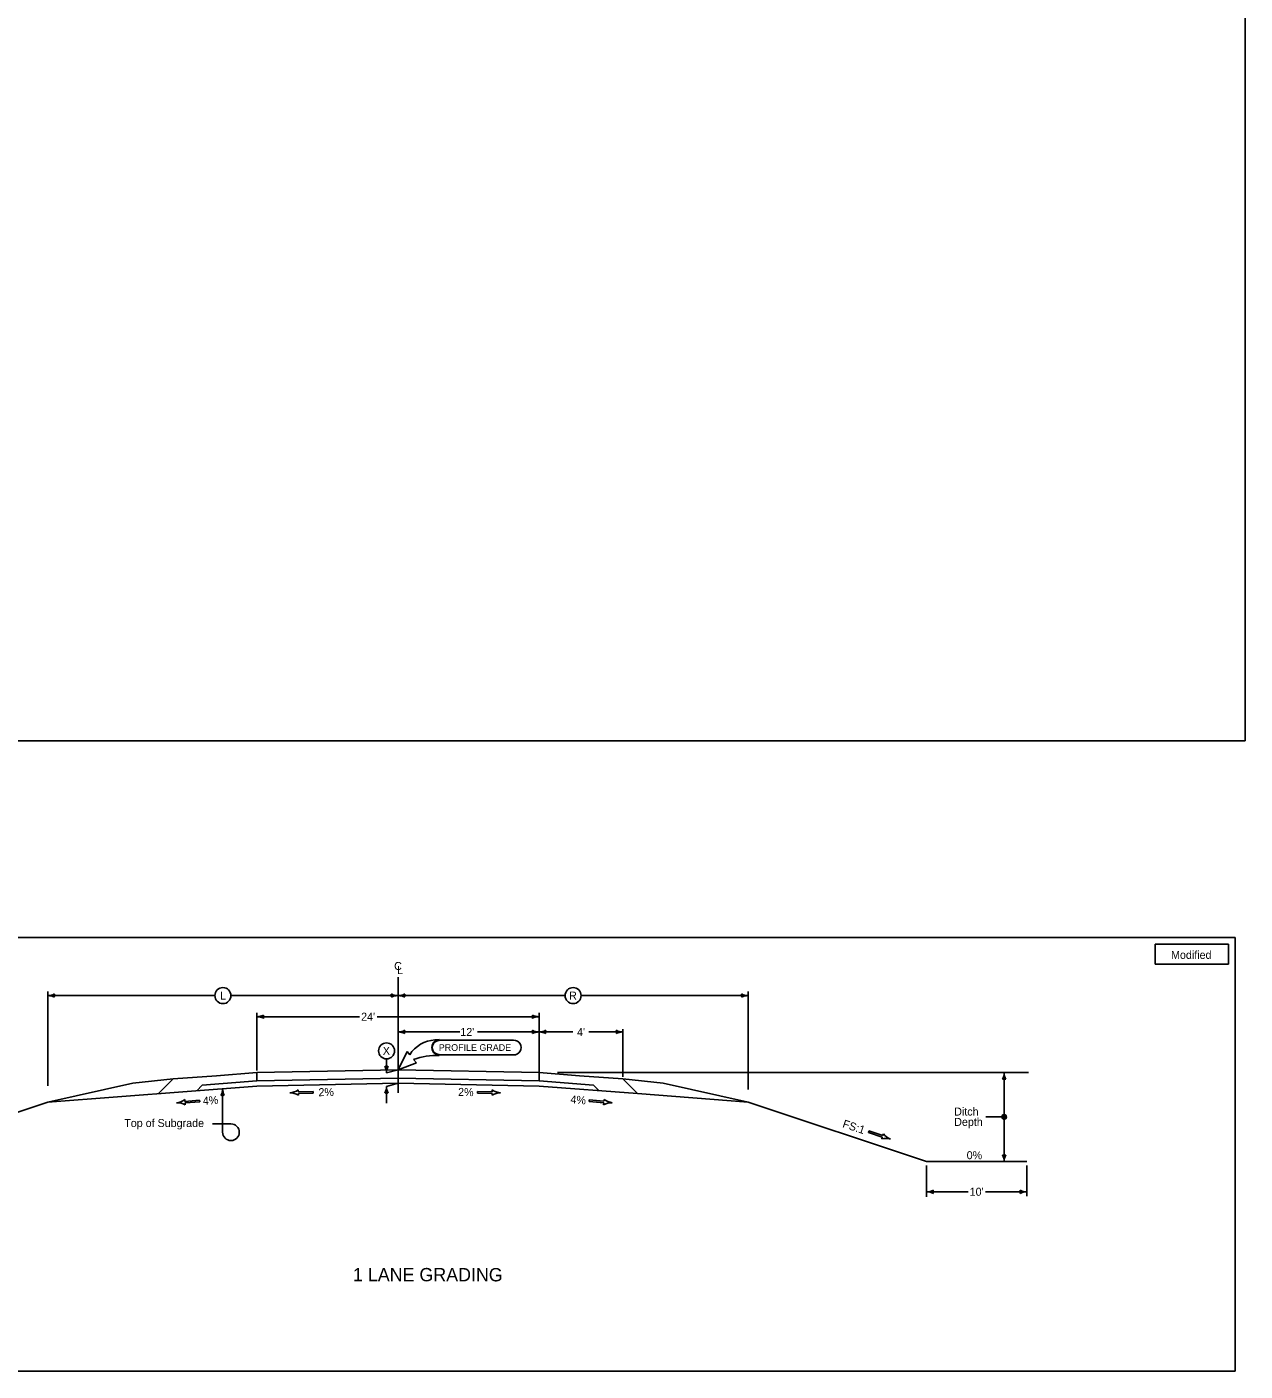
# Model space of a CAD drawing. Extents: x 10133 to 81668, y 6979 to 11018.
# Drawn here: x 11441 to 13268, y 6979 to 8994 of the extents above; entities that cross this region are included whole.
import ezdxf

# ---------------------------------------------------------------- set-up
doc = ezdxf.new("R2010")
doc.units = 0
for name, color, linetype in [('brgPreRevetmentShaded', 7, 'Continuous'), ('brgPreStructureAlternateA', 7, 'Continuous'), ('brgPreStructureNew', 7, 'Continuous'), ('DisFieldPointElev', 7, 'Continuous'), ('dsnCellElements', 7, 'Continuous'), ('dsnShtPlotShapeBatchPrint', 7, 'Continuous'), ('dsnStdShading', 7, 'Continuous'), ('Level 11', 7, 'Continuous')]:
    doc.layers.add(name, color=color, linetype=linetype)

msp = doc.modelspace()

# ---------------------------------------------------------------- linework, layer by layer
at = {"layer": 'brgPreRevetmentShaded'}
for p, q in [((11660.4, 7417), (11599.9, 7410.9)), ((11660.4, 7417), (11638.5, 7395)), ((11725.6, 7421.9), (11660.4, 7417)), ((11725.6, 7421.9), (11786, 7426.5)), ((11786, 7426.5), (11997.6, 7430.8)), ((11786, 7426.5), (11786, 7414)), ((11786, 7414), (11997.6, 7418.2)), ((11997.6, 7430.8), (12209.1, 7426.5)), ((11997.6, 7418.2), (12209.1, 7414)), ((12269.5, 7421.9), (12209.1, 7426.5)), ((12269.5, 7421.9), (12334.7, 7417)), ((12334.7, 7417), (12356.6, 7395)), ((11599.9, 7410.9), (11472.6, 7382.4)), ((11472.6, 7382.4), (11786, 7406.3)), ((11704.2, 7407.8), (11695.9, 7399.4)), ((11704.2, 7407.8), (11786, 7414)), ((11786, 7406.3), (11997.6, 7410.5)), ((12209.1, 7406.3), (11997.6, 7410.5)), ((12290.9, 7407.8), (12209.1, 7414)), ((12356.6, 7395), (12209.1, 7406.3)), ((12290.9, 7407.8), (12299.3, 7399.4))]:
    msp.add_line(p, q, dxfattribs=at)
at = {"layer": 'brgPreStructureAlternateA'}
msp.add_line((11472.6, 7382.4), (11205, 7293.2), dxfattribs=at)
at = {"layer": 'brgPreStructureNew'}
for p, q in [((11997.6, 7396.4), (11997.6, 7569.8)), ((11472.6, 7406.9), (11472.6, 7547.9)), ((11472.6, 7541.9), (11723.1, 7541.9)), ((11747.1, 7541.9), (11997.6, 7541.9)), ((12248.1, 7541.9), (11997.6, 7541.9)), ((12522.6, 7541.9), (12272.1, 7541.9)), ((12522.6, 7401), (12522.6, 7547.9)), ((11786, 7516.3), (11786, 7429.9)), ((12209.1, 7516.3), (12209.1, 7414)), ((11786, 7510.3), (11940, 7510.3)), ((11966.4, 7510.3), (12209.1, 7510.3)), ((12090.4, 7487.4), (11997.6, 7487.4)), ((12209.1, 7487.4), (12116.9, 7487.4)), ((12209.1, 7487.4), (12259.9, 7487.4)), ((12283.9, 7487.4), (12334.7, 7487.4)), ((12334.7, 7491.4), (12334.7, 7420.3)), ((11980.4, 7447.1), (11980.4, 7426)), ((11997.6, 7430.8), (11980.4, 7426)), ((12942.7, 7426.5), (12236.6, 7426.5)), ((12906.3, 7293.2), (12906.3, 7422.6)), ((11997.6, 7410.5), (11980.4, 7405.7)), ((11980.4, 7405.8), (11980.4, 7380.5)), ((12906.3, 7360), (12878.9, 7360)), ((12790.1, 7287.2), (12790.1, 7240.3)), ((12940.1, 7287.2), (12940.1, 7241.1)), ((12790.1, 7247.9), (12852.1, 7247.9)), ((12878.1, 7247.9), (12940.1, 7247.9))]:
    msp.add_line(p, q, dxfattribs=at)
msp.add_lwpolyline([(12906.1, 7356.8), (12907.2, 7357.3), (12909.1, 7357.9), (12909.4, 7359.8), (12909.2, 7361.4), (12908, 7362.9), (12906.3, 7362.8), (12904.4, 7362.5), (12903.5, 7361), (12903.4, 7359.5), (12904.5, 7357.5), (12905.8, 7357.3), (12907.6, 7357.8), (12909.2, 7358.9), (12909.1, 7360.7), (12907.9, 7362.1), (12906.3, 7362.2), (12904.4, 7361.9), (12904.2, 7360.8), (12903.8, 7359.6), (12904.7, 7358.1), (12906, 7358.1), (12907.5, 7358.4), (12908.6, 7359.2), (12908.1, 7360.7), (12906.9, 7361.6), (12905.4, 7361.7), (12905, 7360.9), (12904.5, 7359.9), (12905.3, 7358.7), (12906.4, 7358.4), (12907.4, 7359), (12907.5, 7360.1), (12906.9, 7360.9), (12905.9, 7361.2), (12905.4, 7360.8), (12905.1, 7360.1), (12905.6, 7359.2), (12906.4, 7359.1), (12907.1, 7359.5), (12907, 7360.1), (12906.4, 7360.5), (12905.7, 7360.5), (12905.7, 7360), (12906.4, 7359.7)], dxfattribs=at)
for centre, radius in [((11735.1, 7541.9), 12), ((12260.1, 7541.9), 12), ((11980.4, 7459.1), 12), ((12906.3, 7360), 3.5)]:
    msp.add_circle(centre, radius, dxfattribs=at)
for centre, radius, start, end in [((11472.6, 7563.2), 21.3, 270, 298.0725), ((11472.6, 7520.7), 21.3, 61.9275, 90), ((11490.4, 7541.9), 8.21, 162.2666, 197.7334), ((11979.7, 7541.9), 8.21, 342.2666, 17.7334), ((11997.6, 7563.2), 21.3, 241.9275, 270), ((11997.6, 7520.7), 21.3, 90, 118.0725), ((11997.6, 7563.2), 21.3, 270, 298.0725), ((11997.6, 7520.7), 21.3, 61.9275, 90), ((12015.4, 7541.9), 8.21, 162.2666, 197.7334), ((12504.7, 7541.9), 8.21, 342.2666, 17.7334), ((12522.6, 7563.2), 21.3, 241.9275, 270), ((12522.6, 7520.7), 21.3, 90, 118.0725), ((11786, 7531.6), 21.3, 270, 298.0725), ((11786, 7489.1), 21.3, 61.9275, 90), ((11803.8, 7510.3), 8.21, 162.2666, 197.7334), ((12191.3, 7510.3), 8.21, 342.2666, 17.7333), ((12209.1, 7531.6), 21.3, 241.9275, 270), ((12209.1, 7489.1), 21.3, 90, 118.0725), ((11997.6, 7508.7), 21.3, 270, 298.0725), ((11997.6, 7466.2), 21.3, 61.9275, 90), ((12015.4, 7487.4), 8.21, 162.2666, 197.7334), ((12191.3, 7487.4), 8.21, 342.2667, 17.7334), ((12209.1, 7508.7), 21.3, 241.9275, 270), ((12209.1, 7466.2), 21.3, 90, 118.0725), ((12209.1, 7508.7), 21.3, 270, 298.0725), ((12209.1, 7466.2), 21.3, 61.9275, 90), ((12226.9, 7487.4), 8.21, 162.2666, 197.7334), ((12316.9, 7487.4), 8.21, 342.2667, 17.7334), ((12334.7, 7508.7), 21.3, 241.9275, 270), ((12334.7, 7466.2), 21.3, 90, 118.0725), ((11980.4, 7443.8), 8.21, 252.2666, 287.7333), ((11959.1, 7426), 21.3, 0, 28.0725), ((12001.6, 7426), 21.3, 151.9275, 180), ((12885.1, 7426.5), 21.3, 331.9275, 0), ((12906.3, 7408.7), 8.21, 72.2666, 107.7334), ((12927.6, 7426.5), 21.3, 180, 208.0725), ((11959.1, 7405.8), 21.3, 331.9275, 0), ((11980.4, 7387.9), 8.21, 72.2666, 107.7334), ((12001.6, 7405.8), 21.3, 180, 208.0725), ((12906.3, 7311), 8.21, 252.2666, 287.7334), ((12885.1, 7293.2), 21.3, 0, 28.0725), ((12927.6, 7293.2), 21.3, 151.9275, 180), ((12790.1, 7269.1), 21.3, 270, 298.0725), ((12790.1, 7226.6), 21.3, 61.9275, 90), ((12807.9, 7247.9), 8.21, 162.2666, 197.7334), ((12922.3, 7247.9), 8.21, 342.2666, 17.7334), ((12940.1, 7269.1), 21.3, 241.9275, 270), ((12940.1, 7226.6), 21.3, 90, 118.0725)]:
    msp.add_arc(centre, radius, start, end, dxfattribs=at)
at = {"layer": 'DisFieldPointElev'}
for p, q in [((12334.7, 7417), (12395.2, 7410.9)), ((12334.7, 7417), (12356.6, 7395)), ((12395.2, 7410.9), (12522.6, 7382.4)), ((12522.6, 7382.4), (12356.6, 7395)), ((12522.6, 7382.4), (12790.1, 7293.2)), ((12790.1, 7293.2), (12940.1, 7293.2))]:
    msp.add_line(p, q, dxfattribs=at)
at = {"layer": 'dsnCellElements'}
for p, q in [((13132.5, 7589), (13132.5, 7619)), ((13132.5, 7619), (13242.5, 7619)), ((13242.5, 7619), (13242.5, 7589)), ((13242.5, 7619), (13242.5, 7589)), ((13242.5, 7589), (13132.5, 7589))]:
    msp.add_line(p, q, dxfattribs=at)
msp.add_lwpolyline([(10147.5, 7629), (13252.5, 7629), (13252.5, 6979), (10147.5, 6979), (10147.5, 7629)], dxfattribs=at)
at = {"layer": 'dsnStdShading'}
for p, q in [((11997.6, 7430.8), (12011.3, 7458.1)), ((12011.3, 7458.1), (12015.2, 7453.3)), ((12052.9, 7475.6), (12059.4, 7475.9)), ((12059.4, 7475.9), (12059.4, 7474.6)), ((12059.4, 7475.2), (12170.9, 7475.2)), ((12025.1, 7441), (11997.6, 7430.8)), ((12021, 7446.1), (12025.1, 7441)), ((12059.4, 7453.6), (12059.4, 7452.4)), ((12059.4, 7453), (12171, 7453)), ((11734.7, 7352.3), (11734.7, 7402.3)), ((11835.4, 7396.3), (11835.4, 7396.3)), ((11848.1, 7400.6), (11848.2, 7397.8)), ((11848.2, 7397.8), (11870.2, 7398.2)), ((11870.2, 7395.8), (11848.2, 7395.4)), ((11848.2, 7395.4), (11848.3, 7392.6)), ((11870.2, 7398.2), (11870.2, 7395.8)), ((12138.7, 7397.8), (12116.7, 7398.2)), ((12116.7, 7398.2), (12116.7, 7395.8)), ((12116.7, 7395.8), (12138.7, 7395.4)), ((12138.7, 7395.4), (12138.6, 7392.6)), ((12138.8, 7400.6), (12138.7, 7397.8)), ((12151.5, 7396.3), (12151.5, 7396.3)), ((11665.6, 7381.3), (11665.6, 7381.3)), ((11678, 7386.2), (11678.2, 7383.4)), ((11678.2, 7383.4), (11700.2, 7385)), ((11700.4, 7382.6), (11678.4, 7381)), ((11678.4, 7381), (11678.6, 7378.2)), ((11700.2, 7385), (11700.4, 7382.6)), ((12284.3, 7385.5), (12284.1, 7383.1)), ((12284.1, 7383.1), (12306, 7381.2)), ((12306.2, 7383.6), (12284.3, 7385.5)), ((12306, 7381.2), (12305.8, 7378.4)), ((12306.5, 7386.4), (12306.2, 7383.6)), ((12318.8, 7381.3), (12318.8, 7381.3)), ((11734.7, 7357.1), (11734.7, 7337.1)), ((11729.4, 7349.6), (11719.4, 7349.6)), ((11747.2, 7349.6), (11727.2, 7349.6)), ((12703.5, 7339), (12702.7, 7336.8)), ((12702.7, 7336.8), (12723.6, 7329.8)), ((12724.4, 7332.1), (12703.5, 7339)), ((12723.6, 7329.8), (12722.7, 7327.1)), ((12725.2, 7334.7), (12724.4, 7332.1)), ((12736.1, 7326.9), (12736.1, 7326.9))]:
    msp.add_line(p, q, dxfattribs=at)
for centre, radius, start, end in [((11713.4, 7402.3), 21.3, 331.9275, 0), ((11755.9, 7402.3), 21.3, 180, 208.0725), ((11833.9, 7422.1), 25.8, 273.4978, 303.5278), ((11834.9, 7370.6), 25.8, 58.7638, 88.7938), ((12152, 7370.6), 25.8, 91.2062, 121.2362), ((12153, 7422.1), 25.8, 236.4722, 266.5022), ((11662.7, 7406.9), 25.8, 276.4343, 306.4643), ((11666.4, 7355.5), 25.8, 61.7002, 91.7303), ((11734.7, 7384.5), 8.21, 72.2666, 107.7334), ((12317.7, 7355.5), 25.8, 87.4355, 117.4656), ((12322.1, 7406.9), 25.8, 232.7015, 262.7315), ((11747.2, 7337.1), 12.5, 180, 90), ((12728.9, 7302.1), 25.8, 73.917, 103.947), ((12745.2, 7351), 25.8, 219.183, 249.213)]:
    msp.add_arc(centre, radius, start, end, dxfattribs=at)
for centre, major_axis, start_param, end_param in [((12056, 7427.5), (-48.4, 0), 4.776871, 5.71778), ((12059.4, 7464.1), (-11.2, 0), 4.712389, 7.853982), ((12059.4, 7464.1), (10.6, 0), 1.570796, 4.712389), ((12170.9, 7464.1), (11.2, 0), 4.712389, 7.853982), ((12057.5, 7345.6), (-107.3, 0), 4.694293, 5.059134)]:
    msp.add_ellipse(centre, major_axis=major_axis, ratio=0.995025, start_param=start_param, end_param=end_param, dxfattribs=at)
at = {"layer": 'Level 11'}
msp.add_lwpolyline([(10132.5, 9944), (13267.5, 9944), (13267.5, 7924), (10132.5, 7924)], close=True, dxfattribs=at)

# ---------------------------------------------------------------- texts
at = {"layer": 'brgPreStructureNew'}
for s, p in [('L', (11730.7, 7535.9)), ('R', (12254.1, 7535.9))]:
    msp.add_text(s, height=12, rotation=359.9562, dxfattribs=at).set_placement(p)
for s, p in [("24'", (11942.3, 7504.3)), ("12'", (12091, 7481.4)), ("4'", (12266, 7481.4)), ('X', (11974.8, 7453.1)), ('Ditch', (12831.4, 7362.1)), ('Depth', (12831.4, 7346.6)), ('0%', (12850.1, 7296.7)), ("10'", (12854.6, 7241.9))]:
    msp.add_text(s, height=12, dxfattribs=at).set_placement(p)
at = {"layer": 'dsnShtPlotShapeBatchPrint'}
msp.add_text('Modified', height=12, dxfattribs=at).set_placement((13156.5, 7597))
at = {"layer": 'dsnStdShading'}
for s, height, p in [('C', 12, (11991.8, 7580.3)), ('L', 12, (11996.2, 7574.1)), ('PROFILE GRADE', 10, (12058.7, 7459.1)), ('Top of Subgrade', 12, (11587.2, 7344.9))]:
    msp.add_text(s, height=height, dxfattribs=at).set_placement(p)
for s, height, rotation, p in [('2%', 12, 1.1458, (11878.4, 7391.1)), ('2%', 12, 358.8542, (12087.6, 7391.6)), ('4%', 12, 4.0823, (11705.4, 7378.1)), ('4%', 12, 355.0835, (12255.7, 7380.7)), ('FS:1', 12, 341.565, (12663.1, 7344.9)), ('1 LANE GRADING', 20, 359.9583, (11930.1, 7113.7))]:
    msp.add_text(s, height=height, rotation=rotation, dxfattribs=at).set_placement(p)

doc.saveas('drawing.dxf')
